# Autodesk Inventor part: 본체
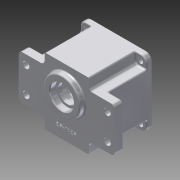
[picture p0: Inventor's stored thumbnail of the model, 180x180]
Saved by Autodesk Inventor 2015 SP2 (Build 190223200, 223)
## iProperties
Created: 2015-06
Part Number: 본체
Material: 알루미늄 6061
Document SubType Name: Modeling
Designer: AMC
Density: 2.7 g/cm^3
Appearance: 알루미늄 - 평지
Mass: 702.679 g
Surface Area: 673.039 cm^2
Volume: 260.252 cm^3
Author: AMC
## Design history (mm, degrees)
sketch "스케치1"
  geometry: L1 (-45, 45)-(45, 45); L2 (45, 45)-(45, -45); L3 (45, -45)-(-45, -45); L4 (-45, -45)-(-45, 45); 3 further points
  constraints: 8 end point, 2 midpoint, 2 parallel, 2 perpendicular, 1 horizontal, 1 horizontal alignment, 1 vertical alignment
  dimensions: "d0" = 90 distance of L1.start L1.end
extrude "돌출1" new body sketch "스케치1" distance "d1" = 70; taper "d2" = 0 deg
sketch "스케치2"
  geometry: L1 (-65, 30)-(65, 30); L2 (65, 30)-(65, -30); L3 (65, -30)-(-65, -30); L4 (-65, -30)-(-65, 30); 3 further points
  constraints: 8 end point, 2 midpoint, 2 parallel, 1 horizontal, 1 horizontal alignment, 1 perpendicular, 1 vertical alignment
  dimensions: "d3" = 60 distance of L3.end L1.start; "d4" = 130 distance of L1.start L1.end
extrude "돌출2" join sketch "스케치2" distance "d5" = 12; taper "d6" = 0 deg
sketch "스케치3"
  geometry: 2 further points
  constraints: 1 coincident
hole "구멍1" sketch "스케치3" at (0, 0) diameter "d7" = 78; stored, may be unused: countersink angle "d11" = 90 deg, drill point angle "d13" = 0 deg; dims "d8" = 6, "d9" = 80, "d10" = 9, "d12" = 61
sketch "스케치4"
  geometry: L1 (65, -30)-(45, -30) reference; L2 (45, -30)-(45, -45) reference; L3 (45, -45)-(-45, -45) reference; L4 (-45, -45)-(-45, -30) reference; L5 (-45, -30)-(-65, -30) reference; L6 (-65, -30)-(-65, 30) reference; L7 (-65, 30)-(-45, 30) reference; L8 (-45, 30)-(-45, 45) reference; L9 (-45, 45)-(45, 45) reference; L10 (45, 45)-(45, 30) reference; L11 (45, 30)-(65, 30) reference; L12 (65, 30)-(65, -30) reference; L13 (-45, 45)-(-30, 45); L14 (-30, 45)-(-30, 30); L15 (-30, 30)-(-45, 30); L16 (-45, 30)-(-45, 45); L17 (45, 45)-(30, 45); L18 (30, 45)-(30, 30); L19 (30, 30)-(45, 30); L20 (45, 30)-(45, 45); L21 (-45, -45)-(-30, -45); L22 (-30, -45)-(-30, -30); L23 (-30, -30)-(-45, -30); L24 (-45, -30)-(-45, -45); L25 (45, -45)-(30, -45); L26 (30, -45)-(30, -30); L27 (30, -30)-(45, -30); L28 (45, -30)-(45, -45); 1 further point
  constraints: 32 end point, 8 parallel, 5 equal length, 4 horizontal, 4 perpendicular
  dimensions: "d14" = 60 distance between parallel lines of L18 L14; "d15" = 60 distance between parallel lines of L23 L15; "d16" = 60 distance between parallel lines of L26 L22
extrude "돌출3" cut sketch "스케치4" distance "d17" = 63; taper "d18" = 0 deg
fillet "모깎기1" dims "d19" = 5
fillet "모깎기2" dims "d20" = 8
sketch "스케치5"
  geometry: C1 r 25 at (0, 11); 1 further point
  constraints: 1 centre point, 1 vertical alignment
  dimensions: "d21" = 11 distance of point (0, 0) C1.centre; "d22" = 50 diameter of C1
extrude "돌출4" join sketch "스케치5" distance "d23" = 7; taper "d24" = 0 deg
sketch "스케치6"
  geometry: C1 r 20.5 at (0, 11); C2 r 14 at (0, -20); 1 further point
  constraints: 2 centre point, 2 vertical alignment
  dimensions: "d25" = 11 distance of point (0, 0) C1.centre; "d26" = 20 distance of C2.centre point (0, 0); "d27" = 41 diameter of C1; "d28" = 28 diameter of C2
extrude "돌출5" join sketch "스케치6" distance "d29" = 7; taper "d30" = 0 deg
hole "구멍2" diameter "d33" = 25; stored, may be unused: countersink angle "d37" = 90 deg, drill point angle "d39" = 0 deg; dims "d31" = 10, "d32" = 10, "d34" = 6, "d35" = 32, "d36" = 8, "d38" = 61
hole "구멍3" diameter "d42" = 25; stored, may be unused: countersink angle "d46" = 90 deg, drill point angle "d48" = 0 deg; dims "d40" = 10, "d41" = 10, "d43" = 6, "d44" = 35, "d45" = 10, "d47" = 61
hole "구멍4" diameter "d51" = 19; stored, may be unused: countersink angle "d55" = 90 deg, drill point angle "d57" = 0 deg; dims "d49" = 10, "d50" = 10, "d52" = 6, "d53" = 22, "d54" = 7, "d56" = 8
fillet "모깎기3" dims "d58" = 2
fillet "모깎기4" dims "d59" = 2
fillet "모깎기5" dims "d60" = 2
fillet "모깎기8" dims "d63" = 2
fillet "모깎기9" dims "d64" = 2
fillet "모깎기10" dims "d65" = 3
fillet "모깎기11" dims "d66" = 2
chamfer "모따기1" distance "d67" = 1; stored, may be unused: second distance "d68" = 2, angle "d69" = 45 deg
chamfer "모따기2" distance "d70" = 1; stored, may be unused: second distance "d71" = 2, angle "d72" = 45 deg
fillet "모깎기12" dims "d73" = 2
sketch "스케치7"
  geometry: L1 (-28, 45)-(28, 45) reference; L2 (30, 43)-(30, 35) reference; L3 (35, 30)-(43, 30) reference; L4 (45, 28)-(45, -28) reference; L5 (43, -30)-(35, -30) reference; L6 (30, -35)-(30, -43) reference; L7 (28, -45)-(-28, -45) reference; L8 (-30, -43)-(-30, -35) reference; L9 (-35, -30)-(-43, -30) reference; L10 (-45, -28)-(-45, 28) reference; L11 (-43, 30)-(-35, 30) reference; L12 (-30, 35)-(-30, 43) reference; L13 (0, 0)-(-39, 0); L14 (0, 0)-(-24.749, 24.749); L15 (-27.577, 21.92)-(-30.26, 24.603); L16 (-21.92, 27.577)-(-24.603, 30.26); C1 r 40 at (0, 0) reference; A1 r 2 centre (-28, 43) between (-28, 45) and (-30, 43) reference; A2 r 2 centre (28, 43) between (30, 43) and (28, 45) reference; A3 r 5 centre (35, 35) between (30, 35) and (35, 30) reference; A4 r 2 centre (43, 28) between (45, 28) and (43, 30) reference; A5 r 2 centre (43, -28) between (43, -30) and (45, -28) reference; A6 r 5 centre (35, -35) between (35, -30) and (30, -35) reference; A7 r 2 centre (28, -43) between (28, -45) and (30, -43) reference; A8 r 2 centre (-28, -43) between (-30, -43) and (-28, -45) reference; A9 r 5 centre (-35, -35) between (-30, -35) and (-35, -30) reference; A10 r 2 centre (-43, -28) between (-45, -28) and (-43, -30) reference; A11 r 2 centre (-43, 28) between (-43, 30) and (-45, 28) reference; A12 r 5 centre (-35, 35) between (-35, 30) and (-30, 35) reference; A13 r 39 centre (0, 0) between (-39, 0) and (-30.26, 24.603) reference; A14 r 39 centre (0, 0) between (-39, 0) and (-30.26, 24.603) reference; A15 r 4 centre (-24.749, 24.749) between (-27.577, 21.92) and (-21.92, 27.577); 1 further point
  constraints: 8 end point, 8 point on circle, 2 parallel, 2 tangent, 1 centre point, 1 coincident, 1 horizontal
  dimensions: "d75" = 45 deg angle of L13 L14; "d76" = 35 distance of L13.start L14.end; "d77" = 8 diameter of A15
extrude "돌출6" join sketch "스케치7" stored distance "d78" = 7; taper "d79" = 0 deg
fillet "모깎기13" dims "d80" = 3.5
hole "구멍5" diameter "d83" = 3.459; stored, may be unused: countersink angle "d87" = 90 deg, drill point angle "d89" = 118 deg; dims "d84" = 12, "d85" = 22, "d86" = 7, "d88" = 15, "d120" = 10, "d121" = 10
fillet "모깎기14" dims "d93" = 2
fillet "모깎기15" dims "d94" = 2
fillet "모깎기16" dims "d95" = 2
fillet "모깎기17" dims "d96" = 2
fillet "모깎기18" dims "d97" = 2
hole "구멍6" diameter "d100" = 7; stored, may be unused: countersink angle "d104" = 90 deg, drill point angle "d106" = 118 deg; dims "d98" = 10, "d99" = 10, "d101" = 12, "d102" = 22, "d103" = 7, "d105" = 15
sketch "스케치8"
  geometry: L1 (55, 17.5)-(55, -17.5); 2 further points
  constraints: 2 end point, 1 horizontal alignment, 1 midpoint, 1 vertical, 1 vertical alignment
  dimensions: "d107" = 35 distance of L1.start L1.end; "d108" = 55 distance of point (0, 0) point (55, 0)
hole "구멍7" sketch "스케치8" at (55, 17.5), (55, -17.5) diameter "d109" = 9; stored, may be unused: countersink angle "d113" = 90 deg, drill point angle "d115" = 118 deg; dims "d110" = 12, "d111" = 22, "d112" = 7, "d114" = 15
sketch "스케치9"
  geometry: L1 (-28, -45)-(28, -45) reference; 2 further points
  constraints: 1 vertical alignment, 1 other
  dimensions: "d116" = 15 distance from line of L1 point (0, -30)
feature "엠보싱1" sketch "스케치9" dims "d7" = 78, "d9" = 80, "d10" = 9, "d12" = 61, "d117" = 0.5, "d118" = 0
fillet "모깎기19" dims "d119" = 0.3
node "솔리드1"
pattern_circular "원형 패턴1" dims "d91" = 360 deg
mirror "대칭1"
mirror "대칭2"
mirror "대칭3"
node "절단 모서리 투영1"
node "절단 모서리 투영2"
